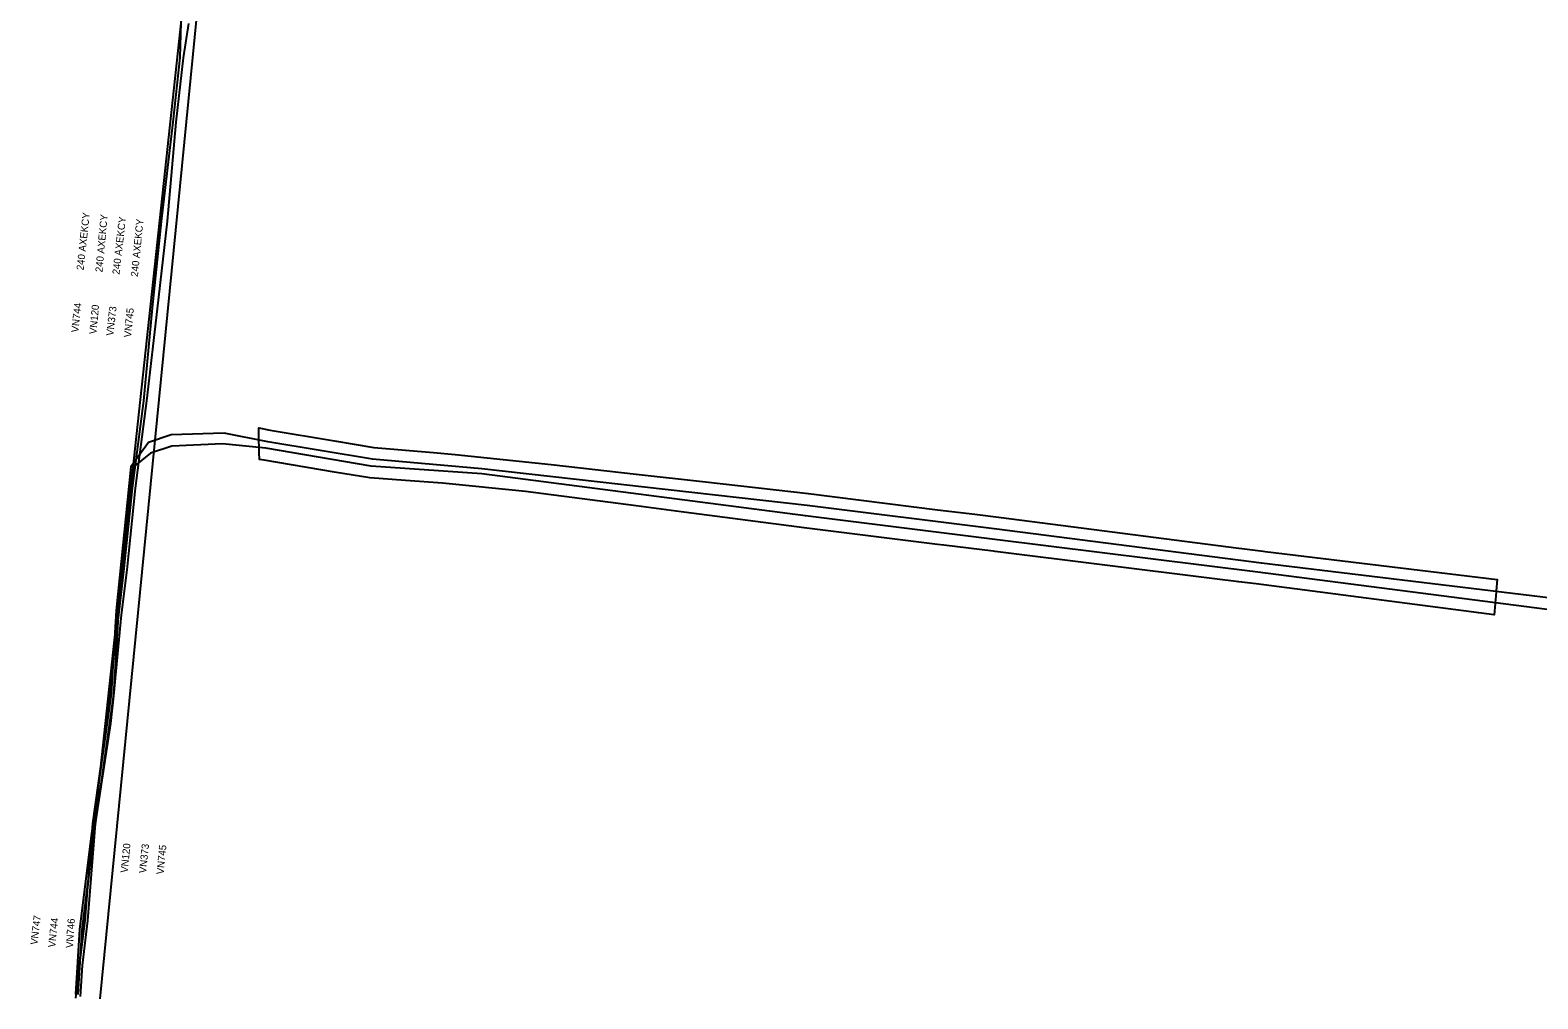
# Model space of a CAD drawing. Extents: x -540182 to -539433, y -1184059 to -1183789.
# Drawn here: x -540112.8 to -539987.7, y -1184024.6 to -1183944.3 of the extents above; entities that cross this region are included whole.
import ezdxf

# ---------------------------------------------------------------- set-up
doc = ezdxf.new("R2010")
doc.units = 0
for name, color, linetype in [('Vrstva 35', 7, 'Continuous'), ('Vrstva 5', 7, 'Continuous'), ('Vrstva 6', 7, 'Continuous'), ('Vrstva 7', 7, 'Continuous')]:
    doc.layers.add(name, color=color, linetype=linetype)

msp = doc.modelspace()

# ---------------------------------------------------------------- linework, layer by layer
at = {"layer": 'Vrstva 35'}
msp.add_lwpolyline([(-540056.73, -1183981.73), (-540048.18, -1183982.7), (-540037.5, -1183984.03), (-540034.41, -1183984.41), (-540032.43, -1183984.66), (-540012.5, -1183987.22), (-540012.25, -1183987.25), (-540010.49, -1183987.48), (-540010.32, -1183987.5), (-539991.06, -1183989.82), (-539991.14, -1183990.76), (-539991.15, -1183990.82), (-539991.19, -1183991.19), (-539991.24, -1183991.75), (-539991.24, -1183991.82), (-539991.33, -1183992.75), (-539992.59, -1183992.59), (-540011.05, -1183990.19), (-540012.5, -1183990.01), (-540014.73, -1183989.73), (-540032.71, -1183987.5), (-540032.87, -1183987.48), (-540036.97, -1183986.97), (-540037.5, -1183986.91), (-540048.56, -1183985.54), (-540059.16, -1183984.16), (-540062.5, -1183983.72), (-540071.66, -1183982.53), (-540078.54, -1183981.82), (-540081.61, -1183981.61), (-540084.59, -1183981.4), (-540087.5, -1183980.91), (-540093.35, -1183979.92), (-540093.74, -1183979.88), (-540093.75, -1183979.29), (-540093.76, -1183978.87), (-540093.78, -1183978.26), (-540093.79, -1183977.87), (-540093.8, -1183977.24), (-540092.86, -1183977.43), (-540087.5, -1183978.32), (-540084.24, -1183978.86), (-540079.29, -1183979.29), (-540077.49, -1183979.45), (-540069.54, -1183980.29), (-540062.5, -1183981.08)], close=True, dxfattribs=at)
at = {"layer": 'Vrstva 5'}
for points in [[(-540083.24, -1183853.72), (-540083.51, -1183853.39), (-540085.89, -1183855.3), (-540088.39, -1183857.77), (-540090.26, -1183861.36), (-540091.97, -1183870.02), (-540092.97, -1183875.92), (-540097.15, -1183914.52), (-540099.98, -1183941.09), (-540109, -1184024.53)], [(-540084.83, -1183862.39), (-540088.84, -1183864.39), (-540091.38, -1183883.23), (-540091.81, -1183887.85), (-540092.67, -1183892.03), (-540094.81, -1183910.88), (-540096.81, -1183921.97), (-540098.27, -1183935.14), (-540098.77, -1183941.17), (-540106.98, -1184024.6)], [(-540100.25, -1183943.62), (-540100.34, -1183946.52), (-540100.93, -1183951.9), (-540101.9, -1183960.12), (-540102.64, -1183967.3), (-540103.35, -1183975), (-540104.29, -1183982.25), (-540104.98, -1183988.92), (-540105.44, -1183992.74), (-540106.2, -1183999.42), (-540106.42, -1184001.79), (-540107.59, -1184010.06), (-540108.21, -1184018.09), (-540108.7, -1184021.85), (-540108.97, -1184024.35)], [(-540099.63, -1183943.7), (-540100.07, -1183946.57), (-540100.66, -1183951.9), (-540101.4, -1183960.11), (-540102.22, -1183967.36), (-540103.11, -1183974.99), (-540104.05, -1183982.24), (-540104.73, -1183989.01), (-540105.2, -1183992.74), (-540105.85, -1183999.47), (-540106.1, -1184001.77), (-540107.35, -1184010.08), (-540108, -1184018.11), (-540108.43, -1184021.83), (-540108.61, -1184024.4)], [(-539821.95, -1184011.26), (-539849.24, -1184007.87), (-539880.01, -1184003.93), (-539905.38, -1184001.2), (-539925.5, -1183998.8), (-539945.21, -1183996.25), (-539974.01, -1183992.89), (-540010.61, -1183988.47), (-540032.56, -1183985.65), (-540048.3, -1183983.69), (-540075.29, -1183980.65), (-540084.37, -1183979.85), (-540093.04, -1183978.41), (-540096.66, -1183977.69), (-540101.06, -1183977.82), (-540102.93, -1183978.45), (-540104.41, -1183980.48), (-540105.62, -1183992.38), (-540106.03, -1183999.34), (-540107.69, -1184011.08), (-540108.66, -1184018.84), (-540109, -1184024.22)], [(-539822.12, -1184012.35), (-539849.32, -1184008.62), (-539880.18, -1184004.98), (-539905.47, -1184002.3), (-539925.6, -1184000.18), (-539945.37, -1183997.3), (-539974.3, -1183993.95), (-540010.92, -1183989.2), (-540032.75, -1183986.49), (-540048.43, -1183984.55), (-540075.28, -1183981.05), (-540084.47, -1183980.41), (-540093.22, -1183978.93), (-540096.79, -1183978.56), (-540101, -1183978.77), (-540102.76, -1183979.35), (-540104.21, -1183980.5), (-540105.42, -1183992.4), (-540105.83, -1183999.36), (-540107.49, -1184011.1), (-540108.46, -1184018.86), (-540108.8, -1184024.24)]]:
    msp.add_lwpolyline(points, dxfattribs=at)

# ---------------------------------------------------------------- texts
at = {"layer": 'Vrstva 6'}
for rotation, p in [(83.83, (-540108.32, -1183964.2)), (84.732, (-540106.76, -1183964.36)), (83.347, (-540105.35, -1183964.55)), (84.38, (-540103.82, -1183964.74))]:
    msp.add_text('240 AXEKCY', height=0.6, rotation=rotation, dxfattribs=at).set_placement(p)
at = {"layer": 'Vrstva 7'}
for s, rotation, p in [('VN744', 83.83, (-540108.76, -1183969.36)), ('VN120', 84.732, (-540107.26, -1183969.5)), ('VN373', 83.547, (-540105.86, -1183969.64)), ('VN745', 84.38, (-540104.39, -1183969.77)), ('VN120', 84.293, (-540104.67, -1184014.17)), ('VN373', 84.202, (-540103.14, -1184014.21)), ('VN745', 84.38, (-540101.69, -1184014.3)), ('VN747', 82.871, (-540112.16, -1184020.15)), ('VN744', 83.83, (-540110.68, -1184020.36)), ('VN746', 86.382, (-540109.2, -1184020.4))]:
    msp.add_text(s, height=0.6, rotation=rotation, dxfattribs=at).set_placement(p)

doc.saveas('drawing.dxf')
